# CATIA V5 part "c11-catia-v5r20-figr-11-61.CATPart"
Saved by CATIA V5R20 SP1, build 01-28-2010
Part number: Part1
Bounding box of the stored display mesh (mm): x -54 to 54, y -91.936 to 93.838, z -12.649 to 110.643
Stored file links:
  D:\v5_r20\psrt_files_downloaded\c11\c11-catia-v5r20-figr-11-61.CATPart
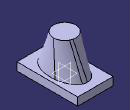
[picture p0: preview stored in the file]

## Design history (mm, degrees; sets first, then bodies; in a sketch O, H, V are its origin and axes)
Set1
  Loft1: Sections (Sketch4; Sketch3)
Body1 (main body)
  Sketch1 on yz-plane, origin (0, 0, 0), H (0, 1, 0), V (0, 0, 1)
    point P1 (93.8379, 11.643)
    line L1 (93.8379, 11.643) -> (93.8379, -12.6487)
    line L2 (93.8379, -12.6487) -> (-91.9362, -12.6487)
    line L3 (-91.9362, -12.6487) -> (-91.9362, 11.643)
    line L4 (-91.9362, 11.643) -> (93.8379, 11.643)
    point P5 (93.8379, 11.643)
    vertical: L1 V, L3 V
    horizontal: L2 H, L4 H
    coincidence: P5 P1
  Pad1: profile Sketch1, direction (1, 0, 0), length 54, mirrored extent
  Sketch2 on face of Pad1, origin (0, 0, 11.643), H (1, 0, 0), V (0, 1, 0)
    circle A1 centre (0, 0) radius 16.7533
    point P1 (16.7533, 0)
    coincidence: A1 P1, P1 H
  Pad2: profile Sketch2, direction (0, 0, 1), length 99
  SewSurface1: SplitPlane Loft1, SewingRemoveFace face of Pad2
  Sketch3 on face of Pad2, origin (0, 0, 110.643), H (1, 0, 0), V (0, 1, 0)
    point P1 (0, 42.8937)
    point P2 (33.9651, 0)
    projected circle E1 centre (0, 0) radius 16.7533 from edge [face of Pad2 | face of Pad2]
    circle A1 centre (0, 0) radius 33.9651
    point P3 (0, 33.9651)
    coincidence: P1 V, P2 H, A1 P2, A1 P3, P3 V
  Sketch4 on face of Pad1, origin (0, 0, 11.643), H (1, 0, 0), V (0, 1, 0)
    ellipse A1 centre (0, 0) semi-axes 69.9141, 43.1918 rotation 90
    point P1 (0, 69.9141)
    point P2 (43.1918, 0)
    coincidence: P1 V, P2 H, A1 P1, A1 P2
